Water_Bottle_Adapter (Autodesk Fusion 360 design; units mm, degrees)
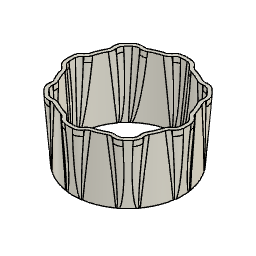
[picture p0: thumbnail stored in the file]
sketch "Sketch1" plane through (0, 0, 0) normal (0, 1, 0) x axis (1, 0, 0)
  line L1 (0, -1.5) -> (0, 0)
  line L2 (30.5, -1.5) -> (0, -1.5)
  line L3 (30.5, 0) -> (30.5, -1.5)
  line L4 (36.7, 0) -> (30.5, 0)
  line L5 (36.7, -1.5) -> (36.7, 0)
  line L6 (37.5, -1.5) -> (36.7, -1.5)
  line L7 (42.5, -67) -> (37.5, -1.5)
  line L8 (47.5, -67) -> (42.5, -67)
  line L9 (47.5, 5) -> (47.5, -67)
  line L10 (0, 5) -> (47.5, 5)
  line L11 (0, 5) -> (0, 0)
  line L12 (32, -1.5) -> (0, -1.5)
  line L13 (37, -251.5) -> (37, -6.5)
  line L14 (0, -251.5) -> (37, -251.5)
  line L15 (0, -1.5) -> (0, -251.5)
  line L16 (0, -136.1679) -> (0, 0)
  line L17 (39, -21.15) -> (37, -21.15)
  arc A1 centre (32, -6.5) radius 5 clockwise from (32, -1.5) to (37, -6.5)
  point P1 (0, 0)
  point P2 (0, 0)
  point P13 (0, 0)
  point P14 (0, -1.5)
  point P7 (36.7, -1.5)
  point P3 (0, -1.5)
  point P21 (37, -21.15)
  point P22 (39, -21.15)
  point P9 (42.5, -67)
  point P10 (47.5, -67)
  point P8 (37.5, -1.5)
  point P16 (0, -251.5)
  coincident P1 P2
  vertical L1
  perpendicular L1 L2
  perpendicular L2 L3
  perpendicular L3 L4
  perpendicular L4 L5
  perpendicular L3 L6
  horizontal L8
  perpendicular L8 L9
  perpendicular L9 L10
  coincident P1 P13
  perpendicular L10 L11
  horizontal L12
  vertical L13
  horizontal L14
  vertical L15
  perpendicular L2 L16
  coincident P14 L16
  coincident P1 L4
  coincident L2 P7
  tangent L12 A1
  tangent L13 A1
  coincident P3 L12
  coincident L13 P21
  coincident L7 P22
  perpendicular L13 L17
  dimension "d1" = 74
  dimension "d2" = 85
  dimension "d3" = 61
  dimension "d4" = 75
  dimension "d5" distance P1 L10 = 5
  dimension "d6" distance P9 P10 = 5
  dimension "d7" distance P1 L2 = 1.5
  dimension "d9" distance P7 P8 = 0.8
  dimension "d10" distance L4 L8 = 67
  dimension "d11" radius A1 = 5
  dimension "d12" distance P14 P16 = 250
  dimension "d13" distance P9 L13 = 5.5
  dimension "d14" angle L7 L9 = 4.365
  dimension "d30" distance P21 P22 = 2
  dimension "d31" distance L8 L17 = 45.85
revolve "Revolve1" sketch "Sketch1" AlongAngle 360 bodies "Cup Holder"
revolve "Revolve2" sketch "Sketch1" AlongAngle 360 bodies "Water Bottle"
sketch "Sketch2" plane through (0, 0, 67) normal (0, 0, 1) x axis (-1, 0, 0)
  line L1 (-41, 0) -> (-43, 0)
  line L2 (-35.507, -20.5) -> (-37.2391, -21.5)
  line L3 (-35.507, -20.5) -> (0, 0)
  line L4 (-41, 0) -> (0, 0)
  circle C1 centre (0, 0) radius 47.5
  circle C2 centre (0, 0) radius 42.5
  arc A1 centre (-35, 0) radius 8 clockwise from (-39.5754, -6.5624) to (-43, 0)
  arc A2 centre (-43.0408, -11.5327) radius 6.0591 clockwise from (-39.5754, -6.5624) to (-37.5545, -14.1045)
  arc A3 centre (-30.3109, -17.5) radius 8 clockwise from (-37.2391, -21.5) to (-37.5545, -14.1045)
  arc A4 centre (-35, 0) radius 6 clockwise from (-38.4316, -4.9218) to (-41, 0)
  arc A5 centre (-43.0408, -11.5327) radius 8.0591 clockwise from (-38.4316, -4.9218) to (-35.7436, -14.9534)
  arc A6 centre (-30.3109, -17.5) radius 6 clockwise from (-35.507, -20.5) to (-35.7436, -14.9534)
  circle C3 centre (0, 0) radius 43
  circle C4 centre (0, 0) radius 36.5
  circle C5 centre (0, 0) radius 37
  point P1 (0, 0)
  point P7 (-30.3109, -17.5)
  point P3 (-35, 0)
  point P17 (0, 0)
  point P4 (-43, 0)
  point P9 (-37.2391, -21.5)
  point P18 (0, 0)
  point P19 (0, 0)
  point P20 (0, 0)
  horizontal L1
  tangent A1 A2
  tangent A2 A3
  coincident P1 L1
  coincident P7 L2
  coincident P1 L2
  coincident P3 L1
  coincident P1 P17
  coincident P4 C3
  coincident P9 C3
  coincident P1 P18
  coincident P17 P19
  coincident P1 P20
  tangent A5 C4
  equal A1 A3
  dimension "d17" = -2
  dimension "d18" angle L3 L4 = 30
  dimension "d19" distance C2 C3 = 0.5
  dimension "d21" distance C4 C5 = 0.5
  dimension "d24" radius A3 = 8
  dimension "d25" radius A5 = 8.0591
extrude "Extrude1" new body sketch "Sketch2" profile of C2 A1 L1 A2 A3 L2 A4 A5 A6 C5 against normal blind 20
draft "Draft1" Angle1 4.4 Angle2 0
sketch "Sketch3" plane through (0, 0, 67) normal (0, 0, 1) x axis (-1, 0, 0)
  line L1 (-38.1039, -9.2052) -> (-42.3789, -5.9888)
  line L2 (-34.2012, -25.7317) -> (-33.4526, -20.4344)
  line L3 (-42.8, 0) -> (0, 0)
  line L4 (-44.5827, -44.5827) -> (0, 0)
  line L5 (-39.6888, -18.4378) -> (-34.2012, -25.7317)
  line L6 (-41.4204, -12.772) -> (-42.3789, -5.9888)
  line L7 (-35.8709, -7.7566) -> (-40.0338, -4.6247)
  line L8 (-31.5783, -25.038) -> (-30.8494, -19.8798)
  line L9 (-33.9064, -14.0445) -> (0, 0)
  line L10 (-35.8709, -7.7566) -> (-38.1039, -9.2052)
  line L11 (-40.0338, -4.6247) -> (-42.3789, -5.9888)
  line L12 (-41.2064, -5.3067) -> (-36.9874, -8.4809)
  line L13 (-39.0969, -6.8938) -> (0, 0)
  line L14 (-30.2642, -30.2642) -> (-28.4964, -28.4964)
  line L15 (-42.8, 0) -> (-40.3, 0)
  circle C1 centre (0, 0) radius 47.5
  circle C2 centre (0, 0) radius 42.5
  circle C3 centre (0, 0) radius 37
  arc A1 centre (0, 0) radius 39.2 clockwise from (-33.4526, -20.4344) to (-38.1039, -9.2052)
  arc A2 centre (0, 0) radius 42.8 clockwise from (-30.2642, -30.2642) to (-34.2012, -25.7317)
  arc A3 centre (0, 0) radius 42.8 clockwise from (-42.3789, -5.9888) to (-42.8, 0)
  arc A4 centre (0, 0) radius 40.3 clockwise from (-40.0338, -4.6247) to (-40.3, 0)
  arc A5 centre (0, 0) radius 36.7 clockwise from (-30.8494, -19.8798) to (-35.8709, -7.7566)
  arc A6 centre (0, 0) radius 40.3 clockwise from (-28.4964, -28.4964) to (-31.5783, -25.038)
  point P5 (0, 0)
  point P10 (0, 0)
  point P11 (-42.8, 0)
  point P4 (0, 0)
  point P12 (0, 0)
  point P14 (-30.2642, -30.2642)
  point P1 (0, 0)
  point P27 (0, 0)
  point P28 (-33.9064, -14.0445)
  point P29 (-36.9874, -8.4809)
  point P30 (-41.2064, -5.3067)
  point P31 (0, 0)
  point P32 (-39.0969, -6.8938)
  concentric C1 A2
  concentric A1 A2
  coincident P5 P10
  coincident P11 A2
  horizontal L3
  coincident P4 P12
  coincident L4 P14
  concentric A2 A3
  tangent A2 L5
  tangent A3 L6
  coincident P1 P27
  midpoint A5 P28
  midpoint L10 P29
  midpoint L11 P30
  coincident P1 P31
  midpoint L12 P32
  parallel L4 L14
  parallel L3 L15
  dimension "d38" angle L2 L5 = 45
  dimension "d39" angle L1 L6 = 45
  dimension "d40" = -2.5
  dimension "d41" distance C2 A3 = 0.3
  dimension "d42" distance C3 A1 = 2.2
  dimension "d43" angle L3 L9 = 22.5
  dimension "d44" angle L3 L13 = 10
  dimension "d47" angle L3 L4 = 45
extrude "Extrude2" new body sketch "Sketch3" profile of C2 C3 A3 A1 L1 L2 A4 L8 L7 A5 A6 L14 L15 against normal blind 45 bodies "Spacer"
draft "Draft2" Angle1 -4.4 Angle2 90
draft "Draft3" Angle1 4.4 Angle2 0
fillet "Fillet2" radius 7 5
circular_pattern "C-Pattern1" TotalAngle 360
combine "Combine1"
named bodies: "Cup Holder", "Water Bottle", "Spacer"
